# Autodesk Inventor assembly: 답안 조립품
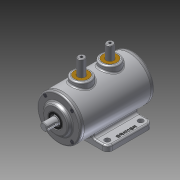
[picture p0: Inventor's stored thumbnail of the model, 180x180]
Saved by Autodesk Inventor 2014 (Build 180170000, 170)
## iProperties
Created: 2014-12
Part Number: 답안 조립품
Document SubType Name: Assembly
Designer: Owner
Author: Owner
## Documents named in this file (10)
- C:\Users\Owner\Desktop\441223V1024\답안 조립품.iam
- C:\Users\Owner\Desktop\441223V1024\M4-소켓머리.ipt
- C:\Users\Owner\Desktop\441223V1024\뒷커버.ipt
- C:\Users\Owner\Desktop\441223V1024\베어링 6203.ipt
- C:\Users\Owner\Desktop\441223V1024\본체.ipt
- C:\Users\Owner\Desktop\441223V1024\부시.ipt
- C:\Users\Owner\Desktop\441223V1024\슬라이더.ipt
- C:\Users\Owner\Desktop\441223V1024\앞커버.ipt
- C:\Users\Owner\Desktop\441223V1024\오일실.ipt
- C:\Users\Owner\Desktop\441223V1024\축.ipt
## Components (11 placed, 3 different names)
1. 7-베어링 6203:1
2. 8-오일실:1
3. 7-베어링 6203:2
4. 9-M4-소켓머리:1
5. 9-M4-소켓머리:3
6. 9-M4-소켓머리:4
7. 9-M4-소켓머리:5
8. 9-M4-소켓머리:2
9. 9-M4-소켓머리:6
10. 9-M4-소켓머리:7
11. 9-M4-소켓머리:8
